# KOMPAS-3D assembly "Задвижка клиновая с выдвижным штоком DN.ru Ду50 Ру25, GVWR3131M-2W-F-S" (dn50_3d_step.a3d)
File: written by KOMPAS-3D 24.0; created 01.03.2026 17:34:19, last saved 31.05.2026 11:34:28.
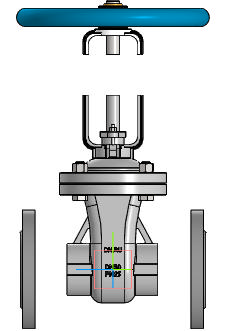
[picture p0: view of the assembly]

Document properties: Автор: R2D2; Полное имя файла: E:\Работа\Зайцев\GVWR3131M-2W-F-S Задвижка клиновая 30нж64нж DN.ru  Ду50-150 Ру25\исходные данные\DN50\dn50_3d_step.a3d

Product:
- Component [detail]: Деталь2  | qty 1  | pos. 1  | Масса: 3.95529; Автор: R2D2; additional columns: Типовые; source file: Деталь2 Деталь2.m3d
- Component [detail]: AS 1110 - M12 x 45  | qty 4  | pos. 2  | Масса: 0.056439; Комментарий: Болты и винты   шестигранные точные   метрические ISO; Автор: R2D2; additional columns: Сталь, мягкая; source file: AS 1110 - M12 x 45 AS 1110 - M12 x 45.m3d
- Component [detail]: ANSI B18.2.4.2M - M12x1,75 - 18  | designation ANSI B18.2.4.2M - M12x1,75  | qty 4  | pos. 3  | Масса: 0.018772; Комментарий: Типы метрических   шестигранных гаек   2; Автор: R2D2; additional columns: Сталь, мягкая; source file: ANSI B18.2.4.2M - M12x1,75 ANSI B18.2.4.2M - M12x1,75 - 18.m3d
- Component [detail]: ANSI B18.2.4.2M - M5x0,8 - 8  | designation ANSI B18.2.4.2M - M5x0,8  | qty 1  | pos. 4  | Масса: 0.00167; Комментарий: Типы метрических   шестигранных гаек   2; Автор: R2D2; additional columns: Сталь, мягкая; source file: ANSI B18.2.4.2M - M5x0,8 ANSI B18.2.4.2M - M5x0,8 - 8.m3d
- Component [detail]: Деталь1  | qty 1  | pos. 5  | Автор: R2D2; additional columns: Типовые; source file: 2.m3d
- Component [detail]: Деталь1  | qty 1  | pos. 5  | Масса: 2.437209; Автор: R2D2; additional columns: Типовые; source file: 1.m3d
- Component [detail]: Деталь1  | designation Деталь1-01  | qty 1  | pos. 6  | Масса: 2.437209; Автор: R2D2; additional columns: Типовые; source file: 1.m3d
- Component [detail]: ANSI B18.2.4.2M - M5x0,8 - 8  | designation ANSI B18.2.4.2M - M5x0,8-01  | qty 1  | pos. 7  | Масса: 0.00167; Комментарий: Типы метрических   шестигранных гаек   2; Автор: R2D2; additional columns: Сталь, мягкая; source file: ANSI B18.2.4.2M - M5x0,8 ANSI B18.2.4.2M - M5x0,8 - 8.m3d
- Component [detail]: Деталь1  | qty 1  | Масса: 0.395685; Автор: R2D2; additional columns: Типовые; source file: 3.m3d
- Part/product: Задвижка клиновая с выдвижным штоком DN.ru Ду50 Ру25  | designation GVWR3131M-2W-F-S
    Масса: 14
    Раздел спецификации: Прочие изделия
    Примечание: D040-08600

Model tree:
1. Массив по концентрической сетке:1  (labels: Грань.Твердое тело1)  (4 pattern instances)
     Шаг 2 = 360
2. Эскиз:1
3. Элемент выдавливания:1  (with: Грань.Элемент вращения:1)  (labels: Грань.Твердое тело1; Грань.Solid1; Твердое тело1)
     Расстояние 1 = 46; Смещение 1 = 1; Расстояние = -125; Ориентация = 2; Ориентация = 2; Расстояние = -362.5

Referenced files in E:\Работа\Зайцев\GVWR3131M-2W-F-S Задвижка клиновая 30нж64нж DN.ru  Ду50-150 Ру25\исходные данные\DN50\: Деталь2 Деталь2.m3d, AS 1110 - M12 x 45 AS 1110 - M12 x 45.m3d, ANSI B18.2.4.2M - M12x1,75 ANSI B18.2.4.2M - M12x1,75 - 18.m3d, ANSI B18.2.4.2M - M5x0,8 ANSI B18.2.4.2M - M5x0,8 - 8.m3d, 3.m3d, 1.m3d, 2.m3d
Referenced files in E:\Работа\Зайцев\GVWR3131M-2W-F-S Задвижка клиновая с выдвижным штоком DN.ru Ду50-200 Ру63\DN50\исходные материалы\: ANSI B18.2.4.2M - M12x1,75 ANSI B18.2.4.2M - M12x1,75 - 18.m3d, AS 1110 - M12 x 45 AS 1110 - M12 x 45.m3d
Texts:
  Программные изделия  и базы данных
  ANSI B18.2.4.2M - M12x1,75
  ANSI B18.2.4.2M - M5x0,8
  Деталь1 - 01
  Деталь1-01
  ANSI B18.2.4.2M - M5x0,8 - 01
  ANSI B18.2.4.2M - M5x0,8-01
  GVWR3131M-2W-F-S
  DN50
  GOST 26.020 Pr3
  PN25
  Деталь2 Деталь2
  AS 1110 - M12 x 45 AS 1110 - M12 x 45 (1)
  ANSI B18.2.4.2M - M12x1,75 ANSI B18.2.4.2M - M12x1,75 - 18 (1)
  ANSI B18.2.4.2M - M5x0,8 ANSI B18.2.4.2M - M5x0,8 - 8
  Деталь1 Деталь1
  Деталь1-01 Деталь1
  ANSI B18.2.4.2M - M12x1,75 ANSI B18.2.4.2M - M12x1,75 - 18 (2)
  AS 1110 - M12 x 45 AS 1110 - M12 x 45 (2)
  ANSI B18.2.4.2M - M12x1,75 ANSI B18.2.4.2M - M12x1,75 - 18 (3)
  AS 1110 - M12 x 45 AS 1110 - M12 x 45 (3)
  ANSI B18.2.4.2M - M12x1,75 ANSI B18.2.4.2M - M12x1,75 - 18 (4)
  AS 1110 - M12 x 45 AS 1110 - M12 x 45 (4)
  ANSI B18.2.4.2M - M5x0,8-01 ANSI B18.2.4.2M - M5x0,8 - 8
  Ось Y.Начало координат
  Ось Z.Начало координат
  Плоскость ZX.Начало координат
  Плоскость XY.Начало координат
  Плоскость ZY.Начало координат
